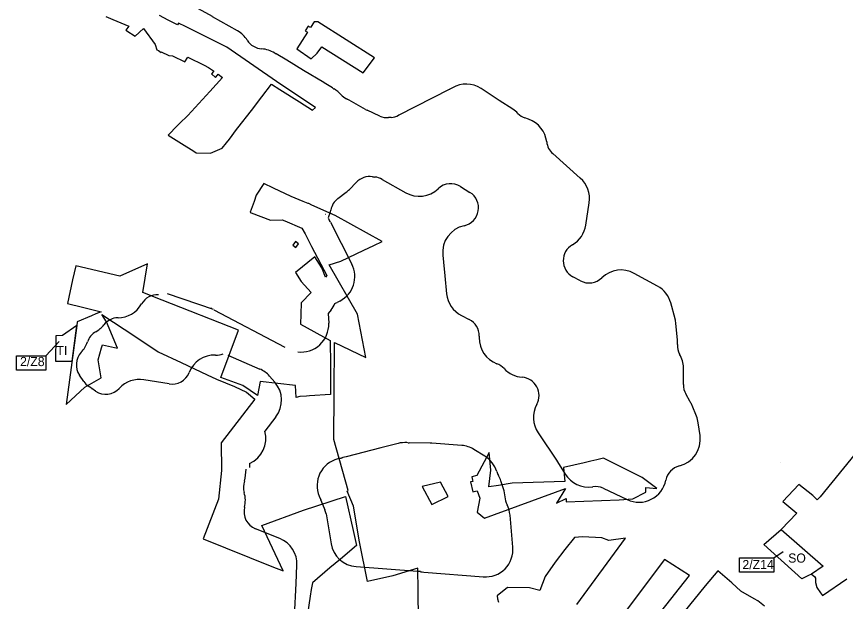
# Model space of a CAD drawing. Extents: x -445049 to -440454, y -1148980 to -1129741.
# Drawn here: x -442999 to -442094, y -1132147 to -1131508 of the extents above; entities that cross this region are included whole.
import ezdxf

# ---------------------------------------------------------------- set-up
doc = ezdxf.new("R2010")
doc.units = 0
for name, color, linetype in [('Vrstva 23', 7, 'Continuous'), ('Vrstva 3', 7, 'Continuous'), ('Vrstva 4', 7, 'Continuous'), ('Vrstva 7', 7, 'Continuous'), ('Vrstva 8', 7, 'Continuous')]:
    doc.layers.add(name, color=color, linetype=linetype)

msp = doc.modelspace()

# ---------------------------------------------------------------- linework, layer by layer
at = {"layer": 'Vrstva 23'}
for p, q in [((-442785.14, -1131508.33), (-442808.34, -1131495.34)), ((-442757.63, -1131524.07), (-442784.9, -1131508.47)), ((-442704.01, -1131555.96), (-442715.43, -1131549.17)), ((-442685.51, -1131567.09), (-442703.85, -1131556.05)), ((-442663.42, -1131580.39), (-442685.51, -1131567.09)), ((-442653.99, -1131586.25), (-442663.03, -1131580.62)), ((-442526.61, -1131588.01), (-442581.37, -1131615.92)), ((-442523.03, -1131585.98), (-442525.73, -1131587.53)), ((-442471.86, -1131599.8), (-442491.71, -1131586.86)), ((-442637.42, -1131598.72), (-442638.59, -1131598.15)), ((-442617.81, -1131609.8), (-442635.63, -1131599.66)), ((-442456.77, -1131609.58), (-442471.82, -1131599.83)), ((-442602.38, -1131616.93), (-442616.23, -1131610.61)), ((-442589.83, -1131618.48), (-442592.63, -1131618.68)), ((-442439.66, -1131620.5), (-442443.66, -1131619.07)), ((-442383.28, -1131684.64), (-442413.36, -1131657.98)), ((-442635.54, -1131697.16), (-442628.23, -1131689.63)), ((-442610.26, -1131683.24), (-442609.96, -1131683.29)), ((-442599.62, -1131686.1), (-442573.99, -1131700.7)), ((-442648.09, -1131707.09), (-442638.95, -1131700.17)), ((-442514.02, -1131693.88), (-442503.81, -1131700.28)), ((-442377.2, -1131735.96), (-442373.51, -1131711.57)), ((-442661.46, -1131723.97), (-442661.36, -1131724.13)), ((-442658.87, -1131728.31), (-442657.15, -1131731.2)), ((-442656.21, -1131732.91), (-442632.86, -1131778.6)), ((-442533.54, -1131769), (-442532.79, -1131776.53)), ((-442532.79, -1131776.57), (-442531.32, -1131791.33)), ((-442531.32, -1131791.33), (-442529.35, -1131811.02)), ((-442298.91, -1131802.64), (-442324.27, -1131788.75)), ((-442383.04, -1131796.85), (-442391.33, -1131792.39)), ((-442834.69, -1131810.61), (-442784.17, -1131828.06)), ((-442787.01, -1131826.88), (-442785.96, -1131826.72)), ((-442645.92, -1131818.96), (-442648.92, -1131820.5)), ((-442279.74, -1131838.27), (-442284.36, -1131821.14)), ((-442783.56, -1131828.59), (-442706.05, -1131869.2)), ((-442513.06, -1131834.8), (-442504.63, -1131839.08)), ((-442279.63, -1131838.68), (-442279.71, -1131838.36)), ((-442277.06, -1131861.35), (-442278.75, -1131843.58)), ((-442493.68, -1131857.25), (-442493.7, -1131858.92)), ((-442277.02, -1131861.82), (-442277.06, -1131861.42)), ((-442768.41, -1131877.95), (-442733.37, -1131893.24)), ((-442273.73, -1131878.96), (-442274.69, -1131877.12)), ((-442925.62, -1131906.93), (-442930.36, -1131900.01)), ((-442270.61, -1131909.01), (-442270.32, -1131893.42)), ((-442832.55, -1131909.56), (-442859.92, -1131905.04)), ((-442722.81, -1131900.96), (-442717.03, -1131907.55)), ((-442270.63, -1131910.14), (-442270.61, -1131909.01)), ((-442917.44, -1131914.27), (-442920.76, -1131911.89)), ((-442912.92, -1131917.36), (-442917.07, -1131914.53)), ((-442263.05, -1131929.11), (-442268, -1131920.42)), ((-442262.76, -1131929.61), (-442263.03, -1131929.14)), ((-442256.29, -1131944.67), (-442261.03, -1131933.13)), ((-442715.82, -1131945.63), (-442727.76, -1131961.14)), ((-442252.41, -1131965.89), (-442254.32, -1131952.01)), ((-442429.23, -1131962.85), (-442408.43, -1131993.86)), ((-442601.2, -1131979.4), (-442638.96, -1131989.07)), ((-442582.21, -1131974.54), (-442601.2, -1131979.4)), ((-442571.48, -1131973.76), (-442572.7, -1131973.67)), ((-442547.32, -1131974.08), (-442570.35, -1131973.8)), ((-442512.75, -1131976.77), (-442545.31, -1131974.18)), ((-442487.52, -1131988.4), (-442499.46, -1131981.09)), ((-442638.97, -1131989.08), (-442642.52, -1131989.99)), ((-442744.53, -1131996.42), (-442744.63, -1132000.64)), ((-442646.75, -1131991.07), (-442648.24, -1131991.45)), ((-442408.03, -1131994.48), (-442399.72, -1132007.91)), ((-442467.05, -1132024), (-442469.99, -1132015.24)), ((-442369.94, -1132021.83), (-442369.69, -1132021.79)), ((-442358.31, -1132023.5), (-442331.99, -1132035.91)), ((-442668.45, -1132032.1), (-442666.71, -1132036.26)), ((-442666.67, -1132036.36), (-442662.27, -1132047)), ((-442661.04, -1132051.33), (-442655.56, -1132084.07)), ((-442456.93, -1132087.64), (-442460.02, -1132052.72)), ((-442711.6, -1132078.29), (-442738.13, -1132067.65)), ((-442693.8, -1132127.45), (-442692.81, -1132107.64)), ((-442628.27, -1132109.03), (-442561.22, -1132114.18)), ((-442554.34, -1132115.05), (-442489.17, -1132120.2)), ((-442695.65, -1132163.23), (-442693.81, -1132127.49))]:
    msp.add_line(p, q, dxfattribs=at)
msp.add_lwpolyline([(-442655.52, -1131828.62), (-442658.63, -1131832.53), (-442658.12, -1131843.34)], dxfattribs=at)
for centre, radius, start, end in [((-442799.8, -1131534.51), 30, 60.22861, 60.75367), ((-442772.52, -1131550.11), 30, 31.97217, 60.22861), ((-442730.11, -1131523.63), 20, 211.97217, 266.50499), ((-442733.16, -1131573.54), 30, 57.67921, 86.50499), ((-442706.42, -1131531.29), 20, 237.67921, 240.88697), ((-442730.75, -1131574.97), 30, 59.2962, 60.88697), ((-442719.32, -1131581.75), 30, 58.95647, 59.2962), ((-442675.2, -1131549.96), 20, 238.95647, 238.95808), ((-442678.89, -1131606.09), 30, 58.09038, 58.95808), ((-442508.09, -1131611.99), 30, 56.89912, 119.87221), ((-442669.85, -1131611.72), 30, 56.37062, 58.09038), ((-442642.16, -1131570.09), 20, 236.37062, 239.77813), ((-442667.32, -1131613.29), 30, 41.53214, 59.77813), ((-442535.69, -1131570.19), 20, 297.01195, 299.87221), ((-442629.9, -1131580.14), 20, 221.53214, 244.22309), ((-442650.46, -1131625.73), 30, 60.35955, 64.22309), ((-442460.94, -1131583.05), 20, 236.89912, 237.05175), ((-442607.92, -1131592.41), 20, 240.35955, 245.46842), ((-442473.09, -1131634.75), 30, 43.65422, 57.05175), ((-442594.07, -1131598.73), 20, 245.46842, 274.13519), ((-442591.27, -1131598.53), 20, 274.13519, 298.06952), ((-442567.74, -1131642.65), 30, 117.01195, 118.06952), ((-442436.91, -1131600.24), 20, 223.65422, 250.29952), ((-442449.77, -1131648.74), 30, 6.58912, 70.29952), ((-442400.1, -1131643.01), 20, 186.58912, 228.45413), ((-442649.75, -1131668.73), 30, 315.8443, 316.72582), ((-442613.35, -1131703), 20, 81.11431, 136.72582), ((-442605.32, -1131653.65), 30, 261.11431, 265.18834), ((-442609.52, -1131703.47), 20, 60.33145, 85.18834), ((-442524.64, -1131710.83), 20, 57.92725, 133.62036), ((-442403.18, -1131707.09), 30, 351.41249, 48.45413), ((-442657.07, -1131676.26), 30, 307.15068, 315.8443), ((-442559.14, -1131674.63), 30, 240.33147, 313.62036), ((-442514.43, -1131717.23), 20, 282.41721, 57.92725), ((-442636.01, -1131723.03), 20, 127.15067, 170.06972), ((-442685.26, -1131714.41), 30, 333.77587, 350.06972), ((-442682.92, -1131746.56), 30, 27.07109, 30.80032), ((-442503.68, -1131766.06), 30, 102.41721, 185.6224), ((-442406.86, -1131731.48), 30, 300.00406, 351.41249), ((-442381.86, -1131774.78), 20, 120.00406, 241.72617), ((-442659.57, -1131792.25), 30, 297.07109, 27.07109), ((-442502.94, -1131773.6), 30, 185.6224, 185.69858), ((-442551.22, -1131793.32), 20, 5.69821, 5.69858), ((-442338.68, -1131815.06), 30, 61.28451, 134.23923), ((-442373.56, -1131779.24), 20, 241.72617, 314.23923), ((-442313.32, -1131828.95), 30, 15.10525, 61.28451), ((-442845.17, -1131832.12), 20, 86.78032, 150.2882), ((-442499.5, -1131808.04), 30, 185.69821, 243.12293), ((-442888.6, -1131807.33), 30, 270.63811, 330.2882), ((-442679.02, -1131809.97), 30, 321.54369, 337.15614), ((-442662.57, -1131793.78), 30, 291.92213, 297.07109), ((-442927.29, -1131826.35), 30, 299.43361, 321.71005), ((-442888.04, -1131857.33), 20, 90.63811, 141.71005), ((-442688.09, -1131844.74), 30, 262.49281, 2.67446), ((-442513.67, -1131856.92), 20, 359.0478, 63.12293), ((-442308.7, -1131846.09), 30, 14.93142, 15.10525), ((-442308.61, -1131846.41), 30, 5.41252, 14.93142), ((-442902.72, -1131869.89), 20, 119.43361, 161.99685), ((-442950.27, -1131854.44), 30, 316.73854, 341.99685), ((-442463.71, -1131859.42), 30, 179.0478, 249.39867), ((-442257.15, -1131859.47), 20, 185.41252, 185.5948), ((-442306.88, -1131864.74), 30, 356.42777, 5.5948), ((-442256.97, -1131867.86), 20, 176.42777, 207.61052), ((-442913.86, -1131888.71), 20, 136.73854, 214.40339), ((-442782.71, -1131908.01), 30, 88.11711, 158.68536), ((-442781.06, -1131858.03), 20, 268.11711, 292.23309), ((-442300.32, -1131892.87), 30, 358.93763, 27.61052), ((-442481.3, -1131906.22), 20, 42.58143, 69.39867), ((-442829.29, -1131889.83), 20, 260.61491, 338.68536), ((-442745.37, -1131920.74), 30, 41.24884, 66.42554), ((-442444.48, -1131872.39), 30, 222.58143, 265.68776), ((-442909.12, -1131895.63), 20, 214.40339, 234.40631), ((-442864.81, -1131934.64), 30, 80.61491, 137.46105), ((-442739.59, -1131927.33), 30, 322.40248, 41.24884), ((-442448.24, -1131922.25), 20, 331.45872, 85.68776), ((-442250.61, -1131909.38), 20, 178.93763, 178.94435), ((-442905.8, -1131898.01), 20, 234.40631, 235.70856), ((-442901.65, -1131900.83), 20, 235.70856, 317.46105), ((-442250.63, -1131910.51), 20, 178.94435, 209.71482), ((-442404.32, -1131946.14), 30, 151.45872, 213.85714), ((-442245.68, -1131919.19), 20, 209.71482, 209.83793), ((-442288.78, -1131944.54), 30, 22.34792, 29.83793), ((-442284.04, -1131956.08), 30, 7.79932, 22.34792), ((-442756.71, -1131969.01), 30, 293.95628, 15.20954), ((-442282.14, -1131969.96), 30, 283.87002, 7.79932), ((-442593.76, -1132008.46), 30, 104.36296, 104.36628), ((-442574.77, -1132003.6), 30, 86.05336, 104.36296), ((-442570.1, -1131953.8), 20, 266.05336, 269.29963), ((-442547.69, -1132004.08), 30, 85.45149, 89.29963), ((-442515.13, -1132006.67), 30, 58.5098, 85.45149), ((-442639.3, -1132020.13), 30, 101.85921, 104.39046), ((-442649.57, -1131971.2), 20, 281.85921, 286.86027), ((-442635.07, -1132019.05), 30, 104.37685, 106.86027), ((-442631.52, -1132018.14), 30, 104.36628, 104.37685), ((-442503.2, -1132013.98), 30, 17.00253, 58.5098), ((-442640.78, -1132020.51), 30, 104.39046, 202.72372), ((-442425.04, -1132005), 20, 31.73644, 33.85714), ((-442270.15, -1132018.51), 20, 103.87002, 168.78139), ((-442800.79, -1132002.49), 52.33, 345.49768, 359.89075), ((-442455.38, -1131999.36), 20, 197.00253, 210.56447), ((-442374.21, -1131992.13), 30, 211.73644, 278.16841), ((-442731.33, -1132022.44), 20, 159.98734, 196.85554), ((-442498.43, -1132024.79), 30, 18.56518, 30.56447), ((-442319.2, -1132008.78), 30, 244.74891, 348.78139), ((-442495.49, -1132033.55), 30, 1.33753, 18.56518), ((-442366.84, -1132041.59), 20, 64.74891, 98.16841), ((-442779.18, -1132036.94), 30, 345.93483, 16.85554), ((-442445.51, -1132032.38), 20, 181.33753, 207.37591), ((-442730.68, -1132049.09), 20, 165.93483, 248.14433), ((-442685.16, -1132043.99), 20, 22.43041, 22.72372), ((-442489.91, -1132055.37), 30, 5.06901, 27.37591), ((-442680.76, -1132054.63), 20, 9.50067, 22.43041), ((-442722.77, -1132106.13), 30, 357.12182, 68.14433), ((-442625.97, -1132079.12), 30, 189.50067, 265.60755), ((-442486.81, -1132090.29), 30, 265.48143, 5.06901), ((-442558.92, -1132084.27), 30, 265.60755, 266.83687), ((-442561.68, -1132134.19), 20, 78.81784, 86.83687), ((-442551.98, -1132085.14), 30, 258.81784, 265.48143), ((-442723.77, -1132125.95), 30, 357.05328, 357.12182)]:
    msp.add_arc(centre, radius, start, end, dxfattribs=at)
at = {"layer": 'Vrstva 3'}
for p, q in [((-442967.34, -1131879), (-442952.76, -1131863.36)), ((-442171.85, -1132099.59), (-442161.46, -1132092.56))]:
    msp.add_line(p, q, dxfattribs=at)
for points in [[(-442999.13, -1131879), (-442967.34, -1131879), (-442967.34, -1131894.4), (-442999.13, -1131894.4)], [(-442209.24, -1132099.59), (-442171.85, -1132099.59), (-442171.85, -1132114.99), (-442209.24, -1132114.99)]]:
    msp.add_lwpolyline(points, close=True, dxfattribs=at)
at = {"layer": 'Vrstva 7'}
for points in [[(-442901.57, -1131508.24), (-442893.86, -1131511.52), (-442876.62, -1131518.64), (-442879.89, -1131523.08), (-442878.67, -1131523.98), (-442869.7, -1131529.78), (-442860.46, -1131521.21), (-442847.68, -1131538.82), (-442845.82, -1131544.77), (-442844.13, -1131545.55), (-442841.3, -1131547.44), (-442841, -1131546.99), (-442832.86, -1131550.74), (-442828.61, -1131551.32), (-442815.12, -1131557.6), (-442812.1, -1131552.55), (-442794.24, -1131561.55), (-442789.47, -1131563.82), (-442784.1, -1131567.66), (-442784, -1131568.37), (-442786.27, -1131570.96), (-442781.76, -1131574.9), (-442779.5, -1131572.4), (-442778.87, -1131571.4), (-442774.2, -1131574.75), (-442788.08, -1131590.07), (-442804.05, -1131607.71), (-442812.19, -1131616.44), (-442821.02, -1131625.16), (-442823.13, -1131627.25), (-442833.65, -1131637.69), (-442818.8, -1131646.95), (-442805.32, -1131655.35), (-442803.05, -1131657.27), (-442787.26, -1131657.33), (-442774.35, -1131652.02), (-442769.89, -1131646.26), (-442766.68, -1131642.05), (-442758.74, -1131631.73), (-442757.29, -1131629.85), (-442742.62, -1131610.8), (-442731.23, -1131596.02), (-442720.56, -1131582.16), (-442711.5, -1131587.93), (-442690.15, -1131601.52), (-442675.97, -1131610.54), (-442672.47, -1131607.71), (-442687.37, -1131597.8), (-442715.22, -1131579.29), (-442769.33, -1131541.71), (-442814.72, -1131519.28), (-442822.12, -1131515.63), (-442823.39, -1131517.5), (-442833.56, -1131512.1), (-442842.85, -1131507.17)], [(-442560.02, -1132158.43), (-442560.28, -1132144.07), (-442560.43, -1132135.57), (-442560.87, -1132110.78), (-442588.01, -1132119.02), (-442615.74, -1132125.39), (-442624.55, -1132082.07), (-442631.01, -1132043.12), (-442638.06, -1132026.52), (-442636.88, -1132025.91), (-442652.52, -1131970.16), (-442652.25, -1131919.67), (-442651.95, -1131864.34), (-442617.55, -1131880.72), (-442626.73, -1131833.42), (-442657.63, -1131779.34), (-442644.94, -1131775.49), (-442619.68, -1131763.51), (-442608.87, -1131758.38), (-442599.87, -1131754.11), (-442650.97, -1131725.63), (-442676.38, -1131714.19), (-442679.82, -1131712.65), (-442680.42, -1131712.4), (-442685.87, -1131710.14), (-442699.1, -1131704.66), (-442718.25, -1131695.8), (-442729.06, -1131690.49), (-442737.48, -1131703.2), (-442739.62, -1131710.23), (-442744.01, -1131722.03), (-442742.8, -1131722.5), (-442721.57, -1131730.84), (-442708.78, -1131730.47), (-442706.21, -1131731.58), (-442687.52, -1131739.57), (-442683.85, -1131745.54), (-442677.06, -1131759.29), (-442660.2, -1131791.09), (-442661.67, -1131792.77), (-442665.52, -1131782.76), (-442673.34, -1131770.69), (-442694.27, -1131787.69), (-442688.06, -1131797.7), (-442677.27, -1131809.5), (-442688.35, -1131821.11), (-442688.7, -1131833.28), (-442689.02, -1131844.34), (-442656.38, -1131861.95), (-442656.33, -1131889.07), (-442656.26, -1131921.1), (-442679.21, -1131922.63), (-442682.29, -1131922.84), (-442689.55, -1131923.32), (-442693.69, -1131924.48), (-442694.25, -1131911.09), (-442733.05, -1131906.89), (-442735.87, -1131922.03), (-442751.85, -1131911.16), (-442775.94, -1131902.63), (-442756.71, -1131850.92), (-442840.13, -1131818.11), (-442861.25, -1131809.85), (-442856.22, -1131778.28), (-442886.26, -1131791.73), (-442934.53, -1131780.44), (-442937.87, -1131795.87), (-442943.42, -1131821.59), (-442927.12, -1131825.63), (-442906.86, -1131830.65), (-442912.57, -1131833.1), (-442917.23, -1131835.11), (-442932.84, -1131841.81), (-442933.12, -1131845.6), (-442945.11, -1131931.99), (-442924.69, -1131912.92), (-442906.55, -1131902.85), (-442909.92, -1131883.24), (-442906.26, -1131869.98), (-442905.36, -1131866.7), (-442888.92, -1131870.38), (-442900.92, -1131841.65), (-442905.86, -1131833.69)], [(-442905.86, -1131833.69), (-442868.89, -1131858.17), (-442844.52, -1131874.3), (-442819.22, -1131886.23), (-442790.99, -1131899.55), (-442780.59, -1131904.45), (-442760.97, -1131912.31), (-442747.89, -1131918.56), (-442738.84, -1131926.19), (-442775.56, -1131973.97), (-442775.35, -1132004.21), (-442778.39, -1132035.21), (-442795.13, -1132078.88), (-442720.26, -1132108.85), (-442707.97, -1132113.8), (-442731.06, -1132064.04), (-442685.75, -1132047.36), (-442639.69, -1132032.42), (-442631.33, -1132069.69), (-442627.71, -1132085.85), (-442645.39, -1132100.83), (-442656.72, -1132110.42), (-442675.84, -1132126.61), (-442677.13, -1132134.16), (-442678.19, -1132141.27), (-442683.66, -1132178.13)], [(-442078.16, -1131980.14), (-442095.71, -1132001.52), (-442121.32, -1132032.71), (-442124.26, -1132036.11), (-442129.2, -1132031.35), (-442144.3, -1132019.27), (-442162, -1132038.04), (-442146.65, -1132050.6), (-442163.82, -1132068.34), (-442118.02, -1132108.73), (-442118.02, -1132108.73), (-442130.73, -1132117.25), (-442127.5, -1132119.77), (-442126.08, -1132121.82), (-442126.37, -1132123.52), (-442126.44, -1132126.56), (-442124.7, -1132131.98), (-442120.75, -1132137.75), (-442118.76, -1132140.66), (-442092.06, -1132122.51)], [(-442387.19, -1132150.6), (-442333.74, -1132078.06), (-442352.12, -1132080.56), (-442359.73, -1132077.56), (-442380.99, -1132076.58), (-442389.53, -1132077.26), (-442400.02, -1132090.51), (-442410.81, -1132104.13), (-442421.45, -1132119.94), (-442427.38, -1132135.31), (-442438.72, -1132132.39), (-442462.74, -1132131.99), (-442474, -1132141.12), (-442473.76, -1132144.18), (-442472.67, -1132147.88)], [(-442295.11, -1132158.42), (-442263.97, -1132118.67), (-442291.1, -1132101.24), (-442345.14, -1132172.9)], [(-442181.94, -1132152.18), (-442189.12, -1132146.59), (-442193.26, -1132144.15), (-442207.7, -1132135.7), (-442217.78, -1132126.81), (-442232.82, -1132113.55), (-442246.83, -1132129.9), (-442270.23, -1132158.64)]]:
    msp.add_lwpolyline(points, dxfattribs=at)
for points in [[(-442607.99, -1131553.24), (-442669.93, -1131514.08), (-442674, -1131513.97), (-442678.01, -1131520.24), (-442680.56, -1131518.68), (-442683.79, -1131523.85), (-442681.32, -1131525.4), (-442692.9, -1131543.48), (-442677.19, -1131554.4), (-442670.87, -1131548.32), (-442665.71, -1131541.3), (-442620.52, -1131569.9)], [(-442691.12, -1131756.43), (-442694.4, -1131753.96), (-442697.36, -1131757.89), (-442694.08, -1131760.36)], [(-442482.92, -1131984.24), (-442496.34, -1132009.66), (-442501.76, -1132010.97), (-442500.87, -1132014.64), (-442500.56, -1132015.93), (-442503.37, -1132016.61), (-442500.76, -1132027.4), (-442497.65, -1132026.64), (-442495.82, -1132026.2), (-442492.89, -1132034.41), (-442495.91, -1132049.69), (-442492, -1132052.75), (-442487.85, -1132055.98), (-442399.27, -1132023.75), (-442409.28, -1132039.85), (-442398.62, -1132034.77), (-442398.59, -1132038.18), (-442340.64, -1132036.04), (-442325.92, -1132035.06), (-442311.53, -1132027.82), (-442311.79, -1132022.68), (-442299.5, -1132023.67), (-442315.76, -1132011.55), (-442357.99, -1131990.77), (-442365.18, -1131992.43), (-442371.87, -1131993.98), (-442378.92, -1131995.61), (-442401.73, -1132000.87), (-442400.08, -1132016.25), (-442457.53, -1132017.89), (-442472.45, -1132020.51), (-442483.34, -1132022.07), (-442480.88, -1132003.85)], [(-442535.86, -1132016.95), (-442555.86, -1132021.4), (-442545.39, -1132041.32), (-442527.52, -1132032.34)]]:
    msp.add_lwpolyline(points, close=True, dxfattribs=at)
at = {"layer": 'Vrstva 8'}
for p, q in [((-442764, -1131870.45), (-442764, -1131870.45)), ((-442164.97, -1131995.27), (-442164.97, -1131995.27))]:
    msp.add_line(p, q, dxfattribs=at)
for points in [[(-442933.12, -1131845.6), (-442948.78, -1131856.65), (-442956.37, -1131856.92), (-442956.47, -1131884.74), (-442938.54, -1131884.68)], [(-442163.82, -1132068.34), (-442118.02, -1132108.73), (-442130.73, -1132117.25), (-442133.92, -1132118.76), (-442141.29, -1132122.26), (-442182.66, -1132084.91)]]:
    msp.add_lwpolyline(points, close=True, dxfattribs=at)

# ---------------------------------------------------------------- texts
at = {"layer": 'Vrstva 3'}
for s, p in [('2/Z8', (-442995.28, -1131890.07)), ('2/Z14', (-442206.07, -1132111.81))]:
    msp.add_text(s, height=10, dxfattribs=at).set_placement(p)
at = {"layer": 'Vrstva 4'}
for s, p in [('TI', (-442955.51, -1131877.97)), ('SO', (-442156.11, -1132104.72))]:
    msp.add_text(s, height=10, dxfattribs=at).set_placement(p)

doc.saveas('drawing.dxf')
